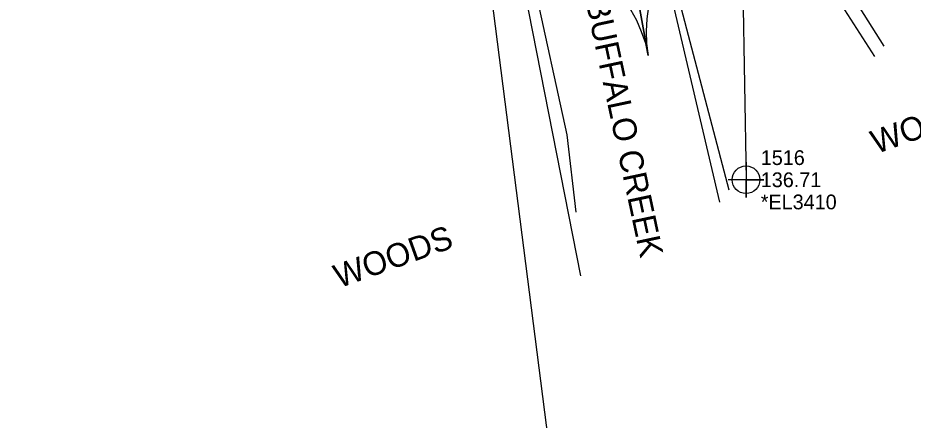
# Model space of a CAD drawing. Extents: x 2248240 to 2249086, y 672625 to 673467.
# Drawn here: x 2248591.2 to 2248742.5, y 672915.3 to 672983.4 of the extents above; entities that cross this region are included whole.
import ezdxf

# ---------------------------------------------------------------- set-up
doc = ezdxf.new("R2010")
doc.units = 0
for name, color, linetype in [('Exist Hydro Jurisdictional Stream or Body of Water', 7, 'Continuous'), ('Exist Hydro Jurisdictional Stream or Body of Water Text', 7, 'Continuous'), ('Exist Hydro River Flow Arrow CELL', 7, 'Continuous'), ('Exist Other Culture Fence Line', 7, 'Continuous'), ('Exist Other Culture Fence Line Cogo Comment', 7, 'Continuous'), ('Exist Other Culture Fence Line Cogo Elevation', 7, 'Continuous'), ('Exist Other Culture Fence Line Cogo Number', 7, 'Continuous'), ('Exist Other Culture Fence Line Cogo Point CELL', 7, 'Continuous'), ('Exist Property Line', 7, 'Continuous'), ('Exist Vegetation Woods Line', 7, 'Continuous'), ('Exist Vegetation Woods Line Text', 7, 'Continuous')]:
    doc.layers.add(name, color=color, linetype=linetype)

msp = doc.modelspace()

# ---------------------------------------------------------------- linework, layer by layer
at = {"layer": 'Exist Hydro Jurisdictional Stream or Body of Water'}
for points in [[(2248706.64, 673017.43), (2248720.41, 673005.91), (2248737.57, 672978.59)], [(2248677.15, 673014.13), (2248678.5, 672988.69), (2248684.02, 672963.61), (2248685.53, 672950.5)], [(2248736.03, 672976.86), (2248718.3, 673004.55), (2248701.69, 673009.51), (2248697.37, 673007), (2248702.46, 672988.28), (2248711.39, 672954.27)]]:
    msp.add_lwpolyline(points, dxfattribs=at)
at = {"layer": 'Exist Hydro River Flow Arrow CELL'}
msp.add_lwpolyline([(2248698.22, 672987.29), (2248697.78, 672985.3), (2248697.51, 672983.24), (2248697.4, 672981.15), (2248697.46, 672979.08), (2248697.76, 672977.05), (2248694.18, 672996.72), (2248697.76, 672977.05), (2248697.32, 672979.05), (2248696.64, 672981.01), (2248695.81, 672982.93), (2248694.83, 672984.76), (2248693.72, 672986.48)], dxfattribs=at)
at = {"layer": 'Exist Other Culture Fence Line'}
msp.add_lwpolyline([(2248745.97, 673059.47), (2248729.51, 673041.49), (2248719.23, 673025.73), (2248716.58, 673011.24), (2248714.82, 672999.21), (2248713.73, 672988.34), (2248714.28, 672955.99)], dxfattribs=at)
at = {"layer": 'Exist Other Culture Fence Line Cogo Point CELL'}
msp.add_lwpolyline([(2248714.28, 672958.99), (2248714.28, 672952.99), (2248714.28, 672955.99), (2248717.28, 672955.99), (2248711.28, 672955.99)], dxfattribs=at)
msp.add_circle((2248714.28, 672955.99), 2.34, dxfattribs=at)
at = {"layer": 'Exist Property Line'}
msp.add_line((2248717.29, 672627.46), (2248666.1, 673027.56), dxfattribs=at)
at = {"layer": 'Exist Vegetation Woods Line'}
for points in [[(2248709.88, 672952.21), (2248697.88, 673003.42), (2248696.7, 673038.35), (2248715.82, 673046.34), (2248755.17, 673065.23)], [(2248274.03, 672898.01), (2248385.83, 672936.02), (2248488.06, 672971.87), (2248541.49, 672985.46), (2248652.67, 673028.73), (2248668.11, 673032.44), (2248686.33, 672939.73)]]:
    msp.add_lwpolyline(points, dxfattribs=at)

# ---------------------------------------------------------------- texts
at = {"layer": 'Exist Hydro Jurisdictional Stream or Body of Water Text'}
msp.add_text('LITTLE BUFFALO CREEK', height=4, rotation=282.0495, dxfattribs=at).set_placement((2248683.16, 673004.79))
at = {"layer": 'Exist Other Culture Fence Line Cogo Comment'}
msp.add_text('*EL3410', height=2.5, dxfattribs=at).set_placement((2248716.78, 672950.99))
at = {"layer": 'Exist Other Culture Fence Line Cogo Elevation'}
msp.add_text('136.71', height=2.5, dxfattribs=at).set_placement((2248716.78, 672954.74))
at = {"layer": 'Exist Other Culture Fence Line Cogo Number'}
msp.add_text('1516', height=2.5, dxfattribs=at).set_placement((2248716.78, 672958.49))
at = {"layer": 'Exist Vegetation Woods Line Text'}
for p in [(2248736.29, 672960.32), (2248645.49, 672937.6)]:
    msp.add_text('WOODS', height=4, rotation=19.6529, dxfattribs=at).set_placement(p)

doc.saveas('drawing.dxf')
